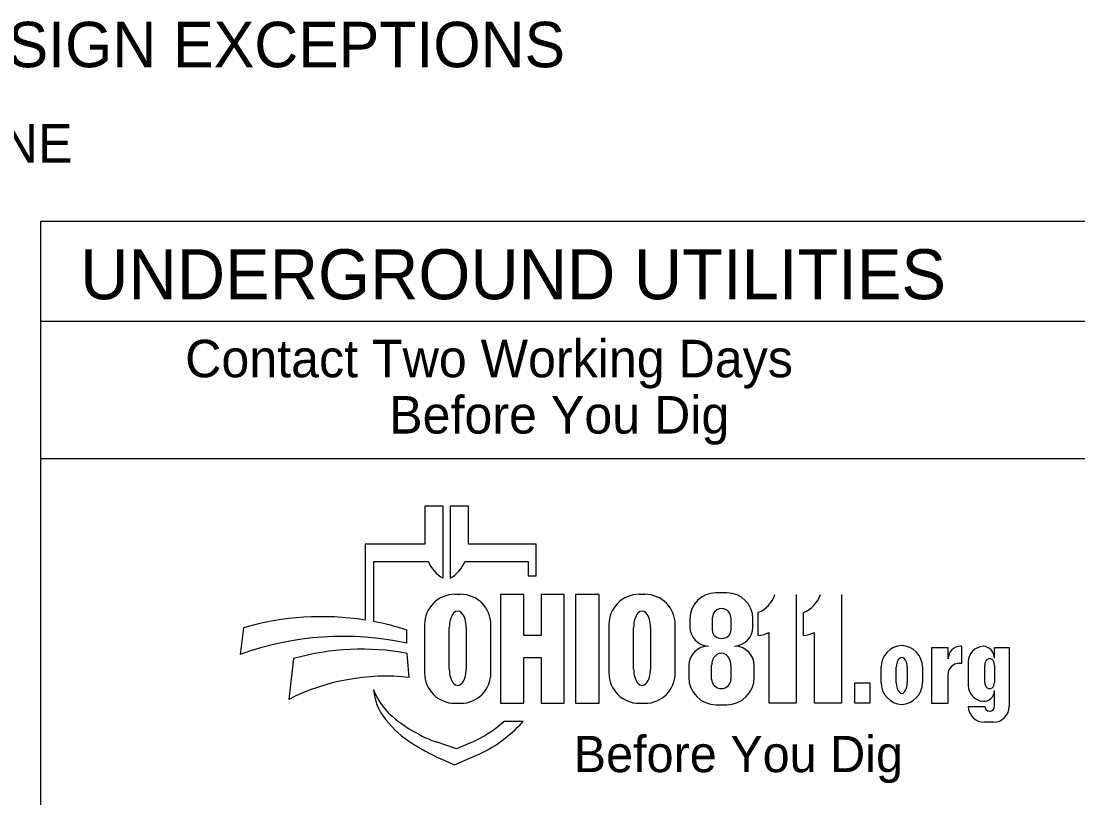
# Model space of a CAD drawing. Extents: x 0 to 96.2, y -27.5 to 31.3.
# Drawn here: x 44.149 to 48.797, y 2.799 to 6.217 of the extents above; entities that cross this region are included whole.
import ezdxf

# ---------------------------------------------------------------- set-up
doc = ezdxf.new("R2010")
doc.units = 0
doc.layers.add('TB1', color=7, linetype='Continuous')

msp = doc.modelspace()

# ---------------------------------------------------------------- linework, layer by layer
at = {"layer": 'TB1'}
for p, q in [((44.2359, 5.3372), (49.4609, 5.3372)), ((44.2359, 2.0372), (44.2359, 5.3372)), ((44.2359, 4.8972), (49.4609, 4.8972)), ((44.2359, 4.2922), (49.4609, 4.2922)), ((46.0048, 4.0827), (45.9247, 4.0827)), ((45.9247, 4.0827), (45.9247, 3.9162)), ((46.0048, 3.7659), (46.0048, 4.0827)), ((46.116, 4.0827), (46.0359, 4.0827)), ((46.0359, 4.0827), (46.0359, 3.7659)), ((46.116, 3.9162), (46.116, 4.0827)), ((45.9247, 3.9162), (45.6619, 3.9162)), ((45.6619, 3.9162), (45.6619, 3.5817)), ((46.4137, 3.9162), (46.116, 3.9162)), ((46.4137, 3.776), (46.4137, 3.9162)), ((45.6996, 3.5751), (45.6996, 3.8393)), ((45.6996, 3.8393), (45.9403, 3.8393)), ((46.1005, 3.8393), (46.3789, 3.8393)), ((46.3789, 3.8393), (46.3789, 3.776)), ((46.3789, 3.776), (46.4137, 3.776)), ((46.0815, 3.6949), (46.0568, 3.6949)), ((46.3594, 3.6935), (46.2579, 3.6935)), ((46.2579, 3.6935), (46.2579, 3.2155)), ((46.8923, 3.6949), (46.8676, 3.6949)), ((47.2534, 3.7015), (47.2045, 3.7015)), ((47.5571, 3.6935), (47.5571, 3.2155)), ((47.7572, 3.6935), (47.7572, 3.2155)), ((47.0905, 3.5875), (47.0905, 3.5512)), ((47.1893, 3.5342), (47.1893, 3.5929)), ((47.2702, 3.5929), (47.2702, 3.5342)), ((47.3674, 3.5512), (47.3674, 3.5875)), ((47.3904, 3.5132), (47.3904, 3.615)), ((47.5905, 3.5132), (47.5905, 3.615)), ((45.1268, 3.5475), (45.1128, 3.4308)), ((45.8457, 3.4798), (45.8457, 3.5378)), ((45.9232, 3.5613), (45.9232, 3.3491)), ((46.0321, 3.3662), (46.0321, 3.5489)), ((46.1065, 3.5489), (46.1065, 3.3662)), ((46.2152, 3.3491), (46.2152, 3.5613)), ((46.7339, 3.5613), (46.7339, 3.3491)), ((46.8428, 3.3662), (46.8428, 3.5489)), ((46.9172, 3.5489), (46.9172, 3.3662)), ((47.0259, 3.3491), (47.0259, 3.5613)), ((47.4387, 3.2155), (47.4387, 3.5271)), ((47.6388, 3.2155), (47.6388, 3.5271)), ((48.226, 3.4589), (48.153, 3.4589)), ((48.153, 3.4589), (48.153, 3.2155)), ((48.226, 3.4118), (48.226, 3.4589)), ((48.2867, 3.4667), (48.2808, 3.4667)), ((48.2867, 3.3921), (48.2867, 3.4667)), ((48.4299, 3.414), (48.4299, 3.4603)), ((48.4299, 3.4603), (48.495, 3.4603)), ((48.495, 3.4603), (48.495, 3.202)), ((45.3474, 3.4123), (45.3255, 3.2328)), ((45.8558, 3.3293), (45.8465, 3.4353)), ((46.3594, 3.2155), (46.3594, 3.4176)), ((48.315, 3.2938), (48.315, 3.3978)), ((47.085, 3.3811), (47.085, 3.3302)), ((47.1858, 3.3213), (47.1858, 3.3824)), ((47.2707, 3.3824), (47.2707, 3.3213)), ((47.3734, 3.3302), (47.3734, 3.3811)), ((47.931, 3.3064), (47.931, 3.3741)), ((47.9983, 3.3052), (47.9983, 3.3741)), ((48.0463, 3.3741), (48.0463, 3.3052)), ((48.1135, 3.3741), (48.1135, 3.3064)), ((48.2753, 3.3921), (48.2867, 3.3921)), ((48.3872, 3.3077), (48.3872, 3.3839)), ((48.4299, 3.3839), (48.4299, 3.3077)), ((48.226, 3.2155), (48.226, 3.3429)), ((45.6986, 3.2756), (45.7032, 3.2489)), ((48.4299, 3.202), (48.4299, 3.2713)), ((46.0568, 3.2155), (46.0815, 3.2155)), ((46.2579, 3.2155), (46.3594, 3.2155)), ((46.8676, 3.2155), (46.8923, 3.2155)), ((47.2059, 3.2093), (47.2525, 3.2093)), ((47.5571, 3.2155), (47.4387, 3.2155)), ((47.7572, 3.2155), (47.6388, 3.2155)), ((48.153, 3.2155), (48.226, 3.2155)), ((48.315, 3.202), (48.3872, 3.202)), ((46.357, 3.1355), (46.2713, 3.1355)), ((46.3546, 3.1328), (46.357, 3.1355)), ((48.4251, 3.1322), (48.3848, 3.1322)), ((46.0636, 3.0147), (45.9748, 3.0453)), ((46.1249, 3.0413), (46.0636, 3.0147)), ((46.0546, 2.9445), (46.1491, 2.9855)), ((45.9988, 2.969), (46.0546, 2.9445))]:
    msp.add_line(p, q, dxfattribs=at)
for points in [[(46.3594, 3.4176), (46.4356, 3.4176), (46.4356, 3.2155), (46.5371, 3.2155), (46.5371, 3.6935), (46.4356, 3.6935), (46.4356, 3.5132), (46.3594, 3.5132), (46.3594, 3.6935)], [(46.5878, 3.2155), (46.6906, 3.2155), (46.6906, 3.6935), (46.5878, 3.6935), (46.5878, 3.2155)], [(47.1715, 3.4676), (47.1715, 3.4675)], [(47.287, 3.4675), (47.287, 3.4676)]]:
    msp.add_lwpolyline(points, dxfattribs=at)
msp.add_lwpolyline([(47.8153, 3.3052), (47.8811, 3.3052), (47.8811, 3.2155), (47.8153, 3.2155)], close=True, dxfattribs=at)
for centre, radius, start, end in [((46.0767, 3.8942), 0.1471, 201.9296, 240.7469), ((45.964, 3.8942), 0.1471, 299.2531, 338.0704), ((46.0568, 3.5613), 0.1337, 90, 180), ((46.0815, 3.5613), 0.1337, 0, 90), ((46.8676, 3.5613), 0.1337, 90, 180), ((46.8923, 3.5613), 0.1337, 0, 90), ((47.2045, 3.5875), 0.114, 90, 180), ((47.2534, 3.5875), 0.114, 0, 90), ((47.3397, 3.7371), 0.1322, 292.5572, 340.7355), ((47.5398, 3.7371), 0.1322, 292.5572, 340.7355), ((45.4705, 2.3732), 1.2235, 81.0007, 106.3144), ((45.4705, 2.3732), 1.2235, 72.1402, 79.2074), ((47.1742, 3.5512), 0.0837, 180, 268.1442), ((47.2837, 3.5512), 0.0837, 272.2058, 0), ((45.5647, 2.1774), 1.3324, 77.8238, 109.8274), ((47.3785, 3.6448), 0.1322, 275.1733, 297.0931), ((47.5786, 3.6448), 0.1322, 275.1733, 297.0931), ((45.6461, 2.3601), 1.0937, 79.44, 105.8467), ((47.1715, 3.3811), 0.0865, 90, 180), ((47.287, 3.3811), 0.0865, 0, 90), ((48.0266, 3.3741), 0.0956, 92.5886, 180), ((48.0179, 3.3741), 0.0956, 0, 87.4114), ((48.2808, 3.4118), 0.0548, 90, 180), ((48.3835, 3.3978), 0.0686, 92.6865, 180), ((48.3775, 3.414), 0.0524, 0, 86.9262), ((46.0568, 3.3491), 0.1337, 180, 270), ((46.0815, 3.3491), 0.1337, 270, 0), ((46.8676, 3.3491), 0.1337, 180, 270), ((46.8923, 3.3491), 0.1337, 270, 0), ((48.2753, 3.3429), 0.0493, 90, 180), ((45.7537, 2.3852), 0.9496, 83.8248, 116.8021), ((47.2059, 3.3302), 0.1209, 180, 270), ((47.2525, 3.3302), 0.1209, 270, 0), ((48.0266, 3.3064), 0.0956, 180, 267.4114), ((48.0179, 3.3064), 0.0956, 272.5886, 0), ((45.9785, 3.3833), 0.2999, 201.0457, 232.5314), ((48.3841, 3.2938), 0.0692, 180, 265.7132), ((48.3832, 3.2713), 0.0467, 264.7825, 0), ((45.9142, 3.2849), 0.2141, 189.6817, 216.0884), ((48.3848, 3.202), 0.0699, 180, 270), ((48.4251, 3.202), 0.0699, 270, 0), ((46.1139, 3.4304), 0.4612, 216.0884, 235.7167), ((46.2661, 3.7586), 0.7728, 232.5314, 241.794), ((45.9107, 3.535), 0.5381, 293.4582, 312.0712), ((45.9107, 3.535), 0.599, 293.4582, 317.8286), ((46.1389, 3.5214), 0.5035, 241.794, 250.9821), ((46.3627, 3.7953), 0.9028, 235.7167, 246.2325)]:
    msp.add_arc(centre, radius, start, end, dxfattribs=at)
for centre, major_axis, ratio, start_param, end_param in [((47.2298, 3.5929), (0.0404, 0), 0.969373, 0, 3.141593), ((46.0693, 3.5489), (0, 0.0723), 0.514403, 4.712389, 7.853982), ((46.88, 3.5489), (0, 0.0723), 0.514403, 4.712389, 7.853982), ((47.2298, 3.5342), (0.0404, 0), 0.818453, 3.141593, 6.283185), ((47.2283, 3.3824), (0, 0.0535), 0.794529, 4.712389, 7.853982), ((48.0223, 3.3741), (0, 0.0434), 0.553236, 4.712389, 7.853982), ((48.4085, 3.3839), (0, 0.0275), 0.777179, 4.712389, 7.853982), ((46.0693, 3.3662), (0, 0.0723), 0.514403, 1.570796, 4.712389), ((46.88, 3.3662), (0, 0.0723), 0.514403, 1.570796, 4.712389), ((47.2283, 3.3213), (0.0425, 0), 0.959837, 3.141593, 6.283185), ((48.0223, 3.3052), (0, 0.046), 0.522014, 1.570796, 4.712389), ((48.4085, 3.3077), (0, 0.0275), 0.777179, 1.570796, 4.712389), ((48.4085, 3.202), (0.0214, 0), 0.959012, 3.141593, 6.283185)]:
    msp.add_ellipse(centre, major_axis=major_axis, ratio=ratio, start_param=start_param, end_param=end_param, dxfattribs=at)

# ---------------------------------------------------------------- texts
for s, height, p in [('DESIGN EXCEPTIONS', 0.2, (43.7178, 6.014)), ('NONE', 0.17, (43.7178, 5.594)), ('UNDERGROUND UTILITIES', 0.22, (44.4085, 4.9933)), ('Contact Two Working Days', 0.165, (44.8703, 4.6499)), ('Before You Dig', 0.165, (45.7674, 4.4024)), ('Before You Dig', 0.15972, (46.5793, 2.9125))]:
    msp.add_text(s, height=height, dxfattribs=at).set_placement(p)

doc.saveas('drawing.dxf')
